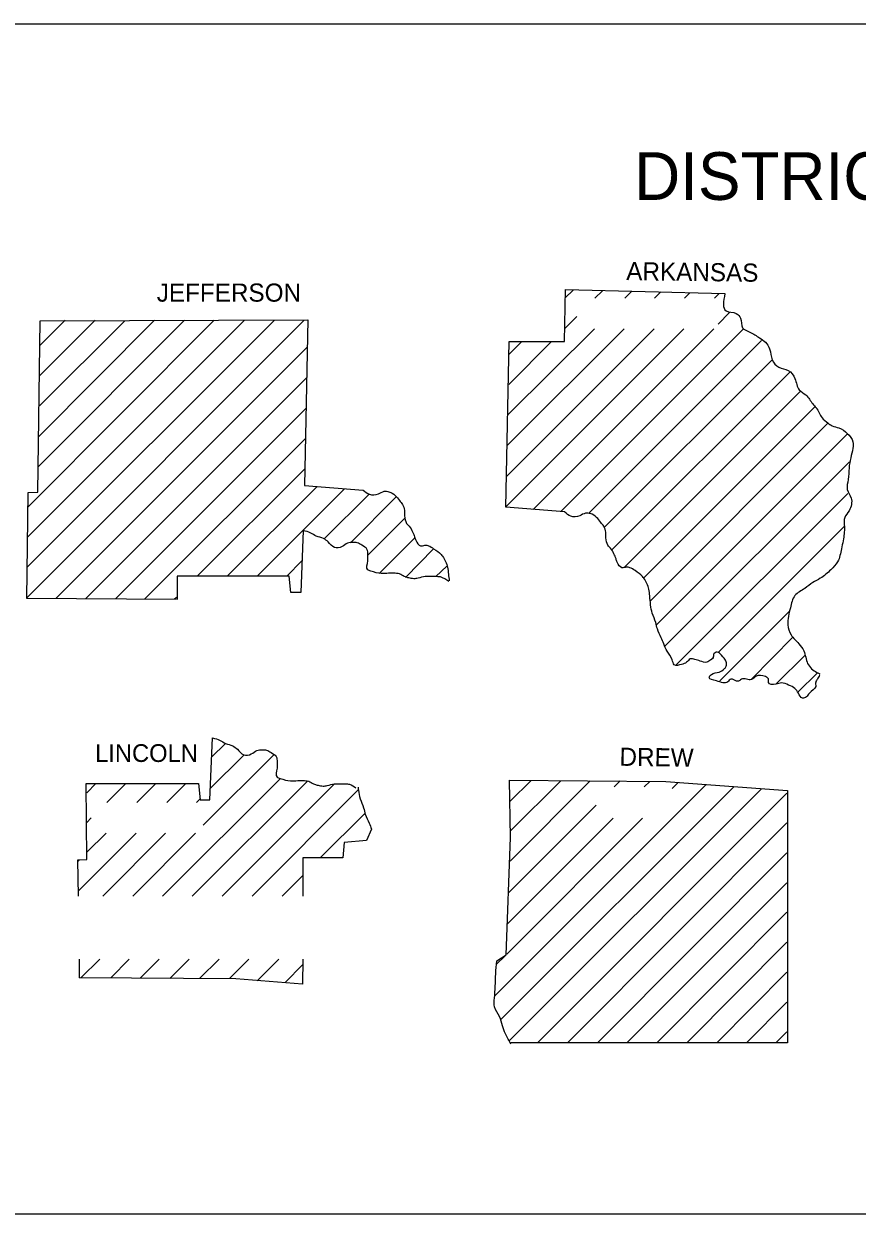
# Model space of a CAD drawing. Extents: x 23481 to 28196, y 1325020 to 1327623.
# Drawn here: x 27755.3 to 27952.8, y 1327341.4 to 1327623.3 of the extents above; entities that cross this region are included whole.
import ezdxf

# ---------------------------------------------------------------- set-up
doc = ezdxf.new("R2010")
doc.units = 0
doc.layers.add('S_ELECTRIC_UTILITIES_ANNOT', color=7, linetype='Continuous')

msp = doc.modelspace()

# ---------------------------------------------------------------- linework, layer by layer
at = {"layer": 'S_ELECTRIC_UTILITIES_ANNOT'}
msp.add_lwpolyline([(28149.74, 1327341.43), (27743.64, 1327341.43), (27743.64, 1327623.33), (28149.74, 1327623.33)], close=True, dxfattribs=at)
for points in [[(27870.34, 1327548.13), (27883.44, 1327548.13), (27883.64, 1327560.43), (27921.44, 1327559.43)], [(27883.54, 1327558.33), (27885.54, 1327560.33)], [(27890.64, 1327558.33), (27892.44, 1327560.13)], [(27897.74, 1327558.33), (27899.34, 1327559.93)], [(27904.74, 1327558.33), (27906.24, 1327559.83)], [(27911.84, 1327558.33), (27913.14, 1327559.63)], [(27918.94, 1327558.33), (27920.04, 1327559.43)], [(27919.84, 1327552.23), (27922.54, 1327554.93)], [(27756.04, 1327487.23), (27756.34, 1327512.33), (27758.64, 1327512.43), (27759.24, 1327553.03), (27822.64, 1327553.23)], [(27756.04, 1327487.43), (27821.74, 1327553.13)], [(27756.14, 1327494.63), (27814.74, 1327553.13)], [(27756.24, 1327501.73), (27807.64, 1327553.13)], [(27756.34, 1327508.93), (27800.44, 1327553.13)], [(27758.84, 1327518.53), (27793.44, 1327553.13)], [(27758.94, 1327525.63), (27786.34, 1327553.13)], [(27759.04, 1327532.83), (27779.24, 1327553.03)], [(27759.14, 1327540.03), (27772.24, 1327553.13)], [(27759.14, 1327547.13), (27765.14, 1327553.13)], [(27822.64, 1327553.23), (27821.84, 1327514.03), (27835.74, 1327512.93)], [(27883.44, 1327551.13), (27886.34, 1327554.03)], [(27869.64, 1327509.03), (27911.74, 1327551.13)], [(27869.74, 1327516.23), (27904.64, 1327551.13)], [(27869.94, 1327523.53), (27897.54, 1327551.13)], [(27870.04, 1327530.73), (27890.54, 1327551.13)], [(27876.04, 1327508.33), (27918.84, 1327551.13)], [(27882.54, 1327507.83), (27925.84, 1327551.13)], [(27762.94, 1327487.23), (27822.54, 1327546.83)], [(27883.44, 1327507.73), (27869.54, 1327508.83), (27870.34, 1327548.13)], [(27870.24, 1327537.93), (27880.34, 1327548.13)], [(27870.34, 1327545.13), (27873.34, 1327548.13)], [(27889.24, 1327507.43), (27930.14, 1327548.33)], [(27892.94, 1327504.13), (27932.64, 1327543.73)], [(27894.74, 1327498.83), (27936.84, 1327540.83)], [(27769.94, 1327487.13), (27822.34, 1327539.53)], [(27897.64, 1327494.63), (27939.34, 1327536.33)], [(27777.04, 1327487.13), (27822.24, 1327532.33)], [(27902.24, 1327492.13), (27942.74, 1327532.63)], [(27903.74, 1327486.63), (27945.94, 1327528.83)], [(27905.24, 1327481.03), (27950.54, 1327526.33)], [(27784.04, 1327487.13), (27822.04, 1327525.13)], [(27796.44, 1327492.53), (27821.94, 1327517.93)], [(27907.24, 1327475.93), (27950.94, 1327519.63)], [(27803.54, 1327492.53), (27824.84, 1327513.73)], [(27810.64, 1327492.53), (27831.34, 1327513.23)], [(27826.54, 1327501.33), (27837.14, 1327511.93)], [(27832.74, 1327500.43), (27843.54, 1327511.33)], [(27909.84, 1327471.43), (27950.54, 1327512.13)], [(27836.74, 1327497.43), (27845.64, 1327506.23)], [(27919.94, 1327474.53), (27949.74, 1327504.33)], [(27821.54, 1327503.33), (27820.94, 1327488.63), (27818.64, 1327488.63), (27818.24, 1327492.53), (27791.64, 1327492.53), (27791.64, 1327487.03)], [(27839.54, 1327493.13), (27847.94, 1327501.53)], [(27845.74, 1327492.23), (27852.44, 1327499.03)], [(27817.64, 1327492.53), (27821.24, 1327496.13)], [(27852.94, 1327492.43), (27855.54, 1327494.93)], [(27791.44, 1327487.03), (27756.04, 1327487.23)], [(27791.04, 1327487.13), (27791.64, 1327487.63)], [(27920.24, 1327467.73), (27936.84, 1327484.33)], [(27927.64, 1327468.03), (27937.64, 1327478.13)], [(27918.14, 1327472.73), (27918.44, 1327473.03), (27918.74, 1327473.33), (27918.74, 1327473.33)], [(27933.54, 1327466.93), (27940.54, 1327473.93)], [(27938.74, 1327465.03), (27943.34, 1327469.63)], [(27768.34, 1327416.73), (27768.14, 1327425.33), (27770.24, 1327425.43), (27770.14, 1327443.43), (27796.74, 1327443.43), (27797.14, 1327439.53), (27799.44, 1327439.53), (27800.04, 1327454.23)], [(27797.84, 1327433.53), (27814.64, 1327450.33)], [(27799.84, 1327449.63), (27803.14, 1327452.93)], [(27799.44, 1327442.13), (27807.44, 1327450.13)], [(27788.24, 1327416.73), (27816.14, 1327444.63)], [(27770.24, 1327441.23), (27772.44, 1327443.43)], [(27775.04, 1327438.93), (27779.54, 1327443.43)], [(27782.14, 1327438.93), (27786.54, 1327443.33)], [(27789.24, 1327438.93), (27793.64, 1327443.33)], [(27795.24, 1327416.73), (27822.44, 1327443.93)], [(27802.34, 1327416.73), (27828.94, 1327443.33)], [(27809.44, 1327416.73), (27834.54, 1327441.93)], [(27866.94, 1327393.13), (27916.94, 1327443.13)], [(27868.34, 1327387.53), (27923.54, 1327442.63)], [(27870.34, 1327444.23), (27907.44, 1327443.93), (27936.24, 1327441.73)], [(27870.64, 1327430.63), (27870.44, 1327444.23)], [(27870.44, 1327382.53), (27930.14, 1327442.13)], [(27870.54, 1327439.23), (27875.54, 1327444.13)], [(27870.54, 1327425.03), (27889.54, 1327444.03)], [(27870.64, 1327432.23), (27882.54, 1327444.03)], [(27895.24, 1327442.63), (27896.64, 1327444.03)], [(27902.34, 1327442.63), (27903.64, 1327443.93)], [(27908.94, 1327442.23), (27910.34, 1327443.63)], [(27936.24, 1327441.73), (27936.24, 1327382.03)], [(27796.24, 1327438.93), (27797.04, 1327439.73)], [(27877.04, 1327382.03), (27936.14, 1327441.13)], [(27825.54, 1327425.83), (27836.14, 1327436.33)], [(27870.24, 1327417.63), (27890.94, 1327438.33)], [(27770.24, 1327434.23), (27771.34, 1327435.33)], [(27869.74, 1327403.03), (27901.94, 1327435.23)], [(27869.94, 1327410.23), (27894.94, 1327435.23)], [(27884.14, 1327382.03), (27936.14, 1327434.13)], [(27768.34, 1327418.03), (27781.94, 1327431.63)], [(27770.24, 1327427.13), (27774.84, 1327431.63)], [(27774.04, 1327416.73), (27788.94, 1327431.63)], [(27781.14, 1327416.73), (27796.04, 1327431.63)], [(27837.74, 1327432.63), (27836.54, 1327429.93), (27831.24, 1327429.43), (27830.94, 1327425.83), (27821.44, 1327425.83), (27821.44, 1327416.73)], [(27867.44, 1327401.43), (27869.64, 1327402.83), (27870.64, 1327430.63)], [(27768.24, 1327425.03), (27768.54, 1327425.33)], [(27891.24, 1327382.03), (27936.14, 1327427.03)], [(27816.54, 1327416.73), (27821.44, 1327421.63)], [(27898.24, 1327382.03), (27936.14, 1327419.93)], [(27905.34, 1327382.03), (27936.14, 1327412.93)], [(27912.44, 1327382.03), (27936.14, 1327405.83)], [(27867.34, 1327400.63), (27869.34, 1327402.53)], [(27768.54, 1327397.43), (27768.54, 1327401.83)], [(27768.84, 1327397.43), (27773.34, 1327401.83)], [(27775.94, 1327397.43), (27780.34, 1327401.83)], [(27782.94, 1327397.33), (27787.44, 1327401.83)], [(27789.94, 1327397.23), (27794.54, 1327401.83)], [(27796.94, 1327397.23), (27801.64, 1327401.83)], [(27804.04, 1327397.23), (27808.64, 1327401.83)], [(27810.64, 1327396.73), (27815.74, 1327401.83)], [(27817.24, 1327396.33), (27821.44, 1327400.53)], [(27821.44, 1327401.83), (27821.34, 1327395.93)], [(27821.34, 1327395.93), (27805.54, 1327397.13), (27768.44, 1327397.43)], [(27919.54, 1327382.03), (27936.14, 1327398.73)], [(27926.54, 1327382.03), (27936.14, 1327391.63)], [(27933.54, 1327382.03), (27936.14, 1327384.63)], [(27936.24, 1327382.03), (27870.74, 1327382.03)]]:
    msp.add_lwpolyline(points, dxfattribs=at)
for points in [[(27921.44, 1327559.43), (27921.74, 1327555.33), (27924.14, 1327554.73), (27925.14, 1327553.63), (27925.64, 1327551.33), (27927.34, 1327550.33), (27929.64, 1327548.93), (27931.04, 1327547.93), (27932.04, 1327546.33), (27932.64, 1327543.73), (27934.24, 1327542.03), (27936.44, 1327541.23), (27938.04, 1327539.33), (27939.04, 1327536.63), (27940.64, 1327535.43), (27942.24, 1327533.33), (27943.04, 1327532.43), (27944.44, 1327530.03), (27945.84, 1327528.83), (27946.84, 1327528.13), (27948.44, 1327527.63), (27950.44, 1327526.33), (27951.74, 1327524.33), (27951.74, 1327522.83), (27951.24, 1327520.53), (27950.84, 1327518.13), (27950.64, 1327515.43), (27950.44, 1327513.03), (27951.34, 1327511.03), (27950.84, 1327508.03), (27949.84, 1327506.43), (27949.74, 1327504.23), (27949.44, 1327500.93), (27949.04, 1327499.03), (27948.14, 1327495.93), (27946.54, 1327494.03)], [(27835.74, 1327512.93), (27837.24, 1327511.93), (27839.34, 1327512.03), (27840.74, 1327512.63), (27841.84, 1327512.53), (27843.34, 1327511.63), (27844.34, 1327510.43), (27845.04, 1327509.53), (27845.54, 1327508.13), (27845.54, 1327506.83), (27846.04, 1327505.03), (27846.64, 1327504.33), (27847.44, 1327503.03), (27847.94, 1327501.83), (27848.24, 1327501.03), (27849.34, 1327499.73), (27850.34, 1327499.83), (27851.24, 1327499.73), (27852.44, 1327499.03), (27854.24, 1327497.63), (27854.54, 1327497.23), (27855.74, 1327494.63), (27855.94, 1327493.03), (27856.14, 1327491.43)], [(27943.84, 1327469.13), (27943.34, 1327468.13), (27942.94, 1327467.43), (27942.94, 1327466.43), (27941.44, 1327464.83), (27940.74, 1327463.93), (27939.84, 1327463.63), (27938.84, 1327464.83), (27938.04, 1327465.93), (27936.54, 1327466.73), (27934.84, 1327467.23), (27933.54, 1327466.93), (27931.74, 1327467.33), (27931.74, 1327468.23), (27931.04, 1327468.73), (27928.84, 1327468.83), (27927.74, 1327468.03), (27925.34, 1327468.13), (27924.64, 1327467.63), (27922.84, 1327468.13), (27922.14, 1327467.53), (27919.44, 1327467.73), (27917.74, 1327468.53), (27918.24, 1327469.23), (27920.04, 1327469.83), (27921.34, 1327470.63), (27921.74, 1327471.23), (27921.74, 1327472.23), (27920.64, 1327473.83), (27919.64, 1327474.53), (27918.74, 1327474.03), (27918.64, 1327473.13), (27918.14, 1327472.73), (27917.14, 1327472.13), (27915.54, 1327472.43), (27914.34, 1327472.83), (27913.24, 1327472.93), (27912.34, 1327472.13), (27911.14, 1327471.63), (27909.44, 1327471.53), (27908.94, 1327472.73), (27907.74, 1327474.73), (27906.94, 1327476.53), (27906.34, 1327477.93), (27905.44, 1327480.03), (27905.04, 1327481.53), (27904.24, 1327483.73), (27903.84, 1327485.73), (27903.64, 1327487.83), (27903.44, 1327489.43), (27902.24, 1327492.03), (27901.94, 1327492.43), (27900.14, 1327493.83), (27898.94, 1327494.53), (27898.04, 1327494.63), (27897.04, 1327494.53), (27895.94, 1327495.83), (27895.64, 1327496.63), (27895.14, 1327497.83), (27894.34, 1327499.13), (27893.74, 1327499.83), (27893.24, 1327501.63), (27893.24, 1327502.93), (27892.74, 1327504.33), (27892.04, 1327505.23), (27891.04, 1327506.43), (27889.54, 1327507.33), (27888.44, 1327507.43), (27887.04, 1327506.83), (27884.94, 1327506.73), (27883.44, 1327507.73)], [(27856.04, 1327491.23), (27854.04, 1327492.33), (27853.04, 1327492.43), (27851.44, 1327492.43), (27850.44, 1327492.43), (27848.74, 1327492.03), (27847.74, 1327491.93), (27846.54, 1327492.13), (27845.74, 1327492.33), (27844.64, 1327492.93), (27843.34, 1327493.23), (27841.74, 1327493.23), (27840.04, 1327493.13), (27837.54, 1327493.73), (27836.84, 1327494.03), (27836.84, 1327496.13), (27836.84, 1327497.63), (27836.64, 1327498.93), (27835.44, 1327499.83), (27834.34, 1327500.43), (27833.34, 1327500.53), (27832.04, 1327500.33), (27830.74, 1327499.53), (27828.94, 1327499.33), (27827.44, 1327500.63), (27826.34, 1327501.43), (27824.64, 1327502.03), (27823.34, 1327502.73), (27821.54, 1327503.33)], [(27946.54, 1327494.03), (27944.04, 1327492.03), (27942.24, 1327491.03), (27940.34, 1327489.63), (27938.04, 1327487.93), (27936.94, 1327485.03), (27936.34, 1327481.03), (27937.14, 1327478.63), (27938.94, 1327476.53), (27940.14, 1327474.83), (27941.04, 1327471.83), (27943.24, 1327469.73), (27943.94, 1327469.43)], [(27800.04, 1327454.23), (27801.84, 1327453.63), (27803.14, 1327452.93), (27804.84, 1327452.33), (27805.94, 1327451.53), (27807.44, 1327450.23), (27809.24, 1327450.43), (27810.54, 1327451.23), (27811.84, 1327451.43), (27812.84, 1327451.33), (27813.94, 1327450.73), (27815.14, 1327449.83), (27815.34, 1327448.53), (27815.34, 1327447.03), (27815.34, 1327444.93), (27816.04, 1327444.63), (27818.54, 1327444.03), (27820.24, 1327444.13), (27821.84, 1327444.13), (27823.14, 1327443.83), (27824.24, 1327443.23), (27825.04, 1327443.03), (27826.24, 1327442.83), (27827.24, 1327442.93), (27828.94, 1327443.33), (27829.94, 1327443.33), (27831.54, 1327443.33), (27832.54, 1327443.23), (27834.04, 1327442.43)], [(27834.54, 1327442.53), (27834.64, 1327441.83), (27835.04, 1327439.83), (27835.84, 1327437.63), (27836.24, 1327436.13), (27837.14, 1327434.03), (27837.74, 1327432.63)], [(27870.74, 1327381.73), (27869.44, 1327384.13), (27868.74, 1327386.03), (27868.04, 1327388.23), (27866.84, 1327390.53), (27866.84, 1327392.63), (27867.04, 1327395.43), (27867.14, 1327398.33), (27867.44, 1327401.43)]]:
    msp.add_spline(points, degree=3, dxfattribs=at)

# ---------------------------------------------------------------- texts
for s, height, p in [('DISTRICT 2', 11.3, (27899.94, 1327581.63)), ('JEFFERSON', 4.3, (27786.84, 1327557.53)), ('LINCOLN', 4.2, (27772.24, 1327448.53))]:
    msp.add_text(s, height=height, dxfattribs=at).set_placement(p)
for s, rotation, p in [('ARKANSAS', 359.2678, (27898.04, 1327562.63)), ('DREW', 359.2258, (27896.44, 1327447.63))]:
    msp.add_text(s, height=4.3, rotation=rotation, dxfattribs=at).set_placement(p)

doc.saveas('drawing.dxf')
